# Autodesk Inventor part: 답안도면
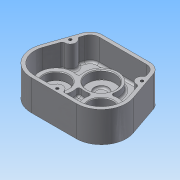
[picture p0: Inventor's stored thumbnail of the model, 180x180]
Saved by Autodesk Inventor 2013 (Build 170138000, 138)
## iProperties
Created: 2014-12
Part Number: 답안도면
Material: 알루미늄 6061
Document SubType Name: Modeling
Designer: Administrator
Mass: 614.49 g
Surface Area: 669.655 cm^2
Volume: 226.749 cm^3
Density: 2.71 g/cm^3
Author: Administrator
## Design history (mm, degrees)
sketch "스케치1"
  geometry: L1 (0, 32.527)-(-32.527, 0); L2 (0, 32.527)-(32.527, 0); L3 (47, 68.527)-(-47, 68.527); L4 (-66.565, 11.723)-(-47, 68.527); L5 (66.565, 11.723)-(47, 68.527); L6 (-32.527, -36)-(32.527, -36); A1 r 36 centre (-32.527, 0) between (-66.565, 11.723) and (-32.527, -36); A2 r 36 centre (32.527, 0) between (32.527, -36) and (66.565, 11.723); 1 further point
  constraints: 12 end point, 4 point on circle, 4 tangent, 2 centre point, 2 horizontal alignment, 1 equal length, 1 horizontal, 1 vertical alignment
  dimensions: "d0" = 72 diameter of A1; "d1" = 72 diameter of A2; "d3" = 90 deg angle of L1 L2; "d4" = 36 distance from line of L3 L1.start; "d5" = 94 distance of L3.start L3.end; "d25" = 46 distance of L1.start L1.end; "d26" = 46 distance of L1.start L2.end
extrude "돌출1" new body sketch "스케치1" distance "d6" = 44; taper "d7" = 0 deg
fillet "모깎기1" dims "d8" = 18
sketch "스케치2"
  geometry: L1 (-51.181, 56.389)-(-66.565, 11.723) reference; L2 (-32.527, -36)-(32.527, -36) reference; L3 (66.565, 11.723)-(51.181, 56.389) reference; L4 (34.162, 68.527)-(-34.162, 68.527) reference; L5 (-46.453, 54.76)-(-61.837, 10.095); L6 (-32.527, -31)-(32.527, -31); L7 (61.837, 10.095)-(46.453, 54.76); L8 (34.162, 63.527)-(-34.162, 63.527); A1 r 18 centre (-34.162, 50.527) between (-34.162, 68.527) and (-51.181, 56.389) reference; A2 r 36 centre (-32.527, 0) between (-66.565, 11.723) and (-32.527, -36) reference; A3 r 36 centre (32.527, 0) between (32.527, -36) and (66.565, 11.723) reference; A4 r 18 centre (34.162, 50.527) between (51.181, 56.389) and (34.162, 68.527) reference; A5 r 13 centre (-34.162, 50.527) between (-34.162, 63.527) and (-46.453, 54.76); A6 r 31 centre (-32.527, 0) between (-61.837, 10.095) and (-32.527, -31); A7 r 31 centre (32.527, 0) between (32.527, -31) and (61.837, 10.095); A8 r 13 centre (34.162, 50.527) between (46.453, 54.76) and (34.162, 63.527); 1 further point
  constraints: 8 end point, 8 point on circle, 4 centre point, 7 other
  dimensions: "d9" = 5 distance between parallel lines of L4 L8
extrude "돌출2" cut sketch "스케치2" distance "d11" = 34; taper "d12" = 0 deg
sketch "스케치3"
  geometry: L1 (-61.837, 10.095)-(-46.453, 54.76) reference; L2 (32.527, -31)-(-32.527, -31) reference; L3 (46.453, 54.76)-(61.837, 10.095) reference; L4 (-34.162, 68.527)-(34.162, 68.527) reference; A1 r 8 centre (-51.7, 39.527) between (-54.305, 31.963) and (-49.095, 47.091); A2 r 8 centre (51.7, 39.527) between (49.095, 47.091) and (54.305, 31.963); A3 r 8 centre (0, -31) between (8, -31) and (-8, -31); 1 further point
  constraints: 8 point on line, 6 point on circle, 3 centre point, 1 midpoint
  dimensions: "d13" = 16 diameter of A1; "d15" = 16 diameter of A2; "d16" = 29 distance from line of L4 A2.centre; "d17" = 29 distance from line of L4 A1.centre; "d18" = 16 diameter of A3
extrude "돌출3" join sketch "스케치3" distance "d19" = 34; taper "d20" = 0 deg
sketch "스케치4"
  geometry: C1 r 24 at (-32.527, 0); C2 r 24 at (32.527, 0); A1 r 31 centre (32.527, 0) between (32.527, -31) and (61.837, 10.095) reference; A2 r 31 centre (-32.527, 0) between (-61.837, 10.095) and (-32.527, -31) reference; 1 further point
  constraints: 2 centre point, 2 coincident
  dimensions: "d21" = 48 diameter of C1; "d22" = 48 diameter of C2
extrude "돌출4" join sketch "스케치4" distance "d23" = 11; taper "d24" = 0 deg
sketch "스케치5"
  geometry: C1 r 24 at (0, 0) reference; C2 r 24 at (-65.054, 0) reference; 1 further point
hole "구멍1" sketch "스케치5" at (-65.054, 0), (0, 0) diameter "d27" = 15.5; stored, may be unused: countersink angle "d31" = 90 deg, drill point angle "d33" = 0 deg; dims "d28" = 6, "d29" = 35, "d30" = 11, "d32" = 21
sketch "스케치6"
  geometry: C1 r 20 at (-32.527, 0); C2 r 20 at (32.527, 0); A1 r 36 centre (-32.527, 0) between (-66.565, 11.723) and (-32.527, -36) reference; A2 r 36 centre (32.527, 0) between (32.527, -36) and (66.565, 11.723) reference; 1 further point
  constraints: 2 centre point, 2 coincident
  dimensions: "d34" = 40 diameter of C1; "d35" = 40 diameter of C2
extrude "돌출5" join sketch "스케치6" distance "d36" = 7; taper "d37" = -10 deg
sketch "스케치7"
  geometry: C1 r 18.766 at (0, 0) reference; C2 r 18.766 at (65.054, 0) reference; 1 further point
hole "구멍2" sketch "스케치7" at (0, 0), (65.054, 0) diameter "d38" = 30; stored, may be unused: countersink angle "d42" = 90 deg, drill point angle "d44" = 0 deg; dims "d39" = 6, "d40" = 35, "d41" = 11, "d43" = 7
sketch "스케치8"
  geometry: L1 (-32.527, 0)-(0, 32.527); L2 (0, 32.527)-(32.527, 0); C1 r 24 at (0, 32.527); A1 r 31 centre (32.527, 0) between (32.527, -31) and (61.837, 10.095) reference; A2 r 31 centre (-32.527, 0) between (-61.837, 10.095) and (-32.527, -31) reference; 1 further point
  constraints: 4 end point, 1 centre point, 1 coincident, 1 perpendicular, 1 vertical alignment
  dimensions: "d45" = 46 distance of L1.end L2.end; "d46" = 48 diameter of C1
extrude "돌출6" join sketch "스케치8" distance "d47" = 11; taper "d48" = 0 deg
hole "구멍3" diameter "d51" = 20; stored, may be unused: countersink angle "d55" = 90 deg, drill point angle "d57" = 0 deg; dims "d49" = 10, "d50" = 10, "d52" = 6, "d53" = 40, "d54" = 12, "d56" = 15
fillet "모깎기2" dims "d58" = 0.3
fillet "모깎기3" dims "d59" = 0.1
chamfer "모따기1" distance "d60" = 1; stored, may be unused: second distance "d61" = 2, angle "d62" = 45 deg
fillet "모깎기4" dims "d63" = 3
fillet "모깎기5" dims "d64" = 3
fillet "모깎기6" dims "d65" = 3
fillet "모깎기7" dims "d66" = 3
sketch "스케치9"
  geometry: A1 r 8 centre (-51.7, 39.527) between (-52.144, 31.539) and (-47.131, 46.094) reference; A2 r 8 centre (51.7, 39.527) between (47.131, 46.094) and (52.144, 31.539) reference; A3 r 8 centre (0, -31) between (7.697, -28.818) and (-7.697, -28.818) reference; 4 further points
  constraints: 3 coincident
hole "구멍4" sketch "스케치9" at (-51.7, 39.527), (0, -31), (51.7, 39.527) diameter "d67" = 4.134; stored, may be unused: countersink angle "d71" = 90 deg, drill point angle "d73" = 118 deg; dims "d68" = 20, "d69" = 40, "d70" = 12, "d72" = 23
node "솔리드1"
node "투영된 루프1"
